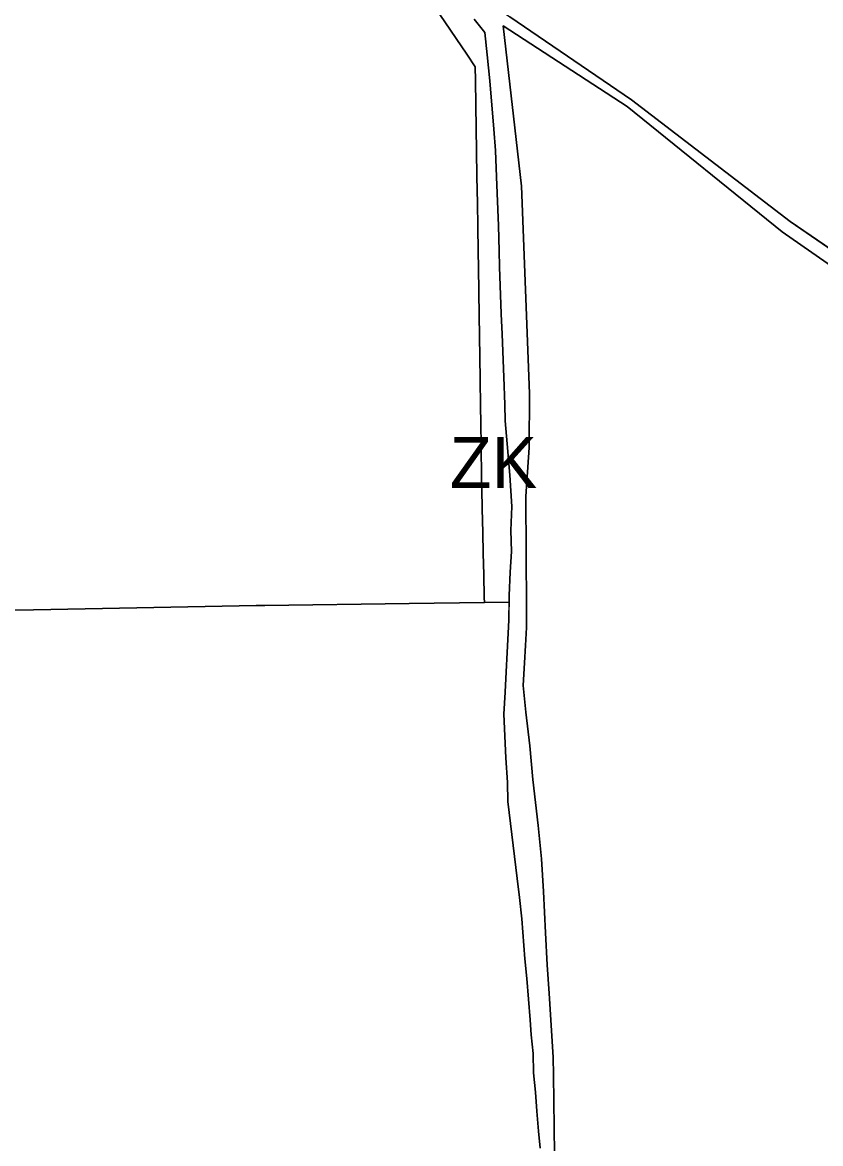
# Model space of a CAD drawing. Extents: x -555509 to -553005, y -1186756 to -1182560.
# Drawn here: x -554047.8 to -553829.3, y -1184851.2 to -1184544.3 of the extents above; entities that cross this region are included whole.
import ezdxf

# ---------------------------------------------------------------- set-up
doc = ezdxf.new("R2010")
doc.units = 0
for name, color, linetype in [('Level 26', 7, 'Continuous'), ('Level 59', 7, 'Continuous'), ('OBRYS_PLOCH', 7, 'Continuous'), ('stav_AP', 7, 'Continuous'), ('stav_AT', 7, 'Continuous'), ('stav_ZK', 7, 'Continuous')]:
    doc.layers.add(name, color=color, linetype=linetype)

msp = doc.modelspace()

# ---------------------------------------------------------------- linework, layer by layer
at = {"layer": 'Level 26'}
for p, q in [((-553881.11, -1184565.44), (-553914.41, -1184542.78)), ((-553911.19, -1184589.14), (-553916.19, -1184545.2)), ((-553916.19, -1184545.2), (-553882.3, -1184567.34)), ((-553837.69, -1184598.76), (-553881.11, -1184565.44)), ((-553882.3, -1184567.34), (-553839.83, -1184601.57)), ((-553918.79, -1184573.46), (-553918.31, -1184579.35)), ((-553918.31, -1184579.35), (-553918.07, -1184586.52)), ((-553908.98, -1184645.9), (-553911.19, -1184589.14)), ((-553803.8, -1184622.03), (-553837.69, -1184598.76)), ((-553839.83, -1184601.57), (-553806.23, -1184625.08)), ((-553917.31, -1184606.77), (-553917.27, -1184611.19)), ((-553917.27, -1184611.19), (-553916.78, -1184624.01)), ((-553916.78, -1184624.01), (-553916.48, -1184629.6)), ((-553909.12, -1184660.61), (-553908.98, -1184645.9)), ((-553910.02, -1184674.09), (-553909.12, -1184660.61)), ((-553914.43, -1184668.19), (-553913.86, -1184676.76)), ((-553909.89, -1184689.55), (-553910.02, -1184674.09)), ((-553913.86, -1184676.76), (-553914.11, -1184683.41)), ((-553909.84, -1184704.54), (-553909.89, -1184689.55)), ((-553914.6, -1184701.16), (-553914.68, -1184707.49)), ((-553909.82, -1184709.89), (-553909.84, -1184704.54)), ((-553910.1, -1184714.83), (-553909.82, -1184709.89)), ((-553910.38, -1184719.64), (-553910.1, -1184714.83)), ((-553910.73, -1184725.83), (-553910.38, -1184719.64)), ((-553909.98, -1184733.08), (-553910.73, -1184725.83)), ((-553908.96, -1184742.29), (-553909.98, -1184733.08)), ((-553908.11, -1184751.52), (-553908.96, -1184742.29)), ((-553906.67, -1184764.14), (-553908.11, -1184751.52)), ((-553905.75, -1184773.22), (-553906.67, -1184764.14)), ((-553905.22, -1184782.2), (-553905.75, -1184773.22)), ((-553904.59, -1184793.52), (-553905.22, -1184782.2)), ((-553904.14, -1184802.28), (-553904.59, -1184793.52)), ((-553903.64, -1184810.15), (-553904.14, -1184802.28)), ((-553902.52, -1184827.53), (-553903.64, -1184810.15)), ((-553902.44, -1184832.5), (-553902.52, -1184827.53)), ((-553902.25, -1184846.67), (-553902.44, -1184832.5)), ((-553902.14, -1184854.22), (-553902.25, -1184846.67))]:
    msp.add_line(p, q, dxfattribs=at)
for points in [[(-553924.15, -1184543.36), (-553921.25, -1184547.01), (-553920.61, -1184553.15), (-553919.86, -1184560.27), (-553918.79, -1184573.46)], [(-553918.07, -1184586.52), (-553917.5, -1184599.96), (-553917.31, -1184606.77)], [(-553916.48, -1184629.6), (-553916.08, -1184641.35), (-553915.74, -1184648.9), (-553915.7, -1184653.31), (-553915.13, -1184659.63), (-553914.43, -1184668.19)], [(-553914.11, -1184683.41), (-553913.94, -1184689.11), (-553914.3, -1184694.82), (-553914.6, -1184701.16)], [(-553914.68, -1184707.49), (-553914.7, -1184707.94), (-553915.09, -1184716.81), (-553915.38, -1184722.04), (-553915.68, -1184727.61), (-553916.05, -1184733.65), (-553915.51, -1184745.58), (-553915.06, -1184752.33), (-553914.93, -1184757.57), (-553912.36, -1184778.63), (-553911.73, -1184783.86), (-553911.1, -1184789.69), (-553910.28, -1184800.63), (-553909.75, -1184806.01), (-553908.82, -1184817.35), (-553908.57, -1184821.45), (-553908.05, -1184826.55), (-553907.89, -1184831.84), (-553907.4, -1184837.11), (-553906.96, -1184842.33), (-553906.53, -1184847.81), (-553906.08, -1184852.45)]]:
    msp.add_lwpolyline(points, dxfattribs=at)
at = {"layer": 'OBRYS_PLOCH'}
for p, q in [((-553881.11, -1184565.44), (-553914.41, -1184542.78)), ((-553911.19, -1184589.14), (-553916.19, -1184545.2)), ((-553916.19, -1184545.2), (-553882.3, -1184567.34)), ((-553882.3, -1184567.34), (-553916.19, -1184545.2)), ((-553916.19, -1184545.2), (-553911.19, -1184589.14)), ((-553837.69, -1184598.76), (-553881.11, -1184565.44)), ((-553882.3, -1184567.34), (-553839.83, -1184601.57)), ((-553839.83, -1184601.57), (-553882.3, -1184567.34)), ((-553918.31, -1184579.35), (-553918.79, -1184573.46)), ((-553918.79, -1184573.46), (-553918.31, -1184579.35)), ((-553918.07, -1184586.52), (-553918.31, -1184579.35)), ((-553918.31, -1184579.35), (-553918.07, -1184586.52)), ((-553908.98, -1184645.9), (-553911.19, -1184589.14)), ((-553911.19, -1184589.14), (-553908.98, -1184645.9)), ((-553803.8, -1184622.03), (-553837.69, -1184598.76)), ((-553839.83, -1184601.57), (-553806.23, -1184625.08)), ((-553806.23, -1184625.08), (-553839.83, -1184601.57)), ((-553917.27, -1184611.19), (-553917.31, -1184606.77)), ((-553917.31, -1184606.77), (-553917.27, -1184611.19)), ((-553916.78, -1184624.01), (-553917.27, -1184611.19)), ((-553917.27, -1184611.19), (-553916.78, -1184624.01)), ((-553916.48, -1184629.6), (-553916.78, -1184624.01)), ((-553916.78, -1184624.01), (-553916.48, -1184629.6)), ((-553909.12, -1184660.61), (-553908.98, -1184645.9)), ((-553908.98, -1184645.9), (-553909.12, -1184660.61)), ((-553910.02, -1184674.09), (-553909.12, -1184660.61)), ((-553909.12, -1184660.61), (-553910.02, -1184674.09)), ((-553913.86, -1184676.76), (-553914.43, -1184668.19)), ((-553914.43, -1184668.19), (-553913.86, -1184676.76)), ((-553909.89, -1184689.55), (-553910.02, -1184674.09)), ((-553910.02, -1184674.09), (-553909.89, -1184689.55)), ((-553914.11, -1184683.41), (-553913.86, -1184676.76)), ((-553913.86, -1184676.76), (-553914.11, -1184683.41)), ((-553909.84, -1184704.54), (-553909.89, -1184689.55)), ((-553909.89, -1184689.55), (-553909.84, -1184704.54)), ((-553921.37, -1184703.05), (-553914.62, -1184702.96)), ((-553914.62, -1184702.96), (-553921.37, -1184703.05)), ((-553914.6, -1184701.16), (-553914.68, -1184707.49)), ((-553914.68, -1184707.49), (-553914.62, -1184702.96)), ((-553914.62, -1184702.96), (-553914.6, -1184701.16)), ((-553909.82, -1184709.89), (-553909.84, -1184704.54)), ((-553909.84, -1184704.54), (-553909.82, -1184709.89)), ((-553910.1, -1184714.83), (-553909.82, -1184709.89)), ((-553909.82, -1184709.89), (-553910.1, -1184714.83)), ((-553910.38, -1184719.64), (-553910.1, -1184714.83)), ((-553910.1, -1184714.83), (-553910.38, -1184719.64)), ((-553910.73, -1184725.83), (-553910.38, -1184719.64)), ((-553910.38, -1184719.64), (-553910.73, -1184725.83)), ((-553909.98, -1184733.08), (-553910.73, -1184725.83)), ((-553910.73, -1184725.83), (-553909.98, -1184733.08)), ((-553908.96, -1184742.29), (-553909.98, -1184733.08)), ((-553909.98, -1184733.08), (-553908.96, -1184742.29)), ((-553908.11, -1184751.52), (-553908.96, -1184742.29)), ((-553908.96, -1184742.29), (-553908.11, -1184751.52)), ((-553906.67, -1184764.14), (-553908.11, -1184751.52)), ((-553908.11, -1184751.52), (-553906.67, -1184764.14)), ((-553905.75, -1184773.22), (-553906.67, -1184764.14)), ((-553906.67, -1184764.14), (-553905.75, -1184773.22)), ((-553905.22, -1184782.2), (-553905.75, -1184773.22)), ((-553905.75, -1184773.22), (-553905.22, -1184782.2)), ((-553904.59, -1184793.52), (-553905.22, -1184782.2)), ((-553905.22, -1184782.2), (-553904.59, -1184793.52)), ((-553904.14, -1184802.28), (-553904.59, -1184793.52)), ((-553904.59, -1184793.52), (-553904.14, -1184802.28)), ((-553903.64, -1184810.15), (-553904.14, -1184802.28)), ((-553904.14, -1184802.28), (-553903.64, -1184810.15)), ((-553902.52, -1184827.53), (-553903.64, -1184810.15)), ((-553903.64, -1184810.15), (-553902.52, -1184827.53)), ((-553902.44, -1184832.5), (-553902.52, -1184827.53)), ((-553902.52, -1184827.53), (-553902.44, -1184832.5)), ((-553902.25, -1184846.67), (-553902.44, -1184832.5)), ((-553902.44, -1184832.5), (-553902.25, -1184846.67)), ((-553902.14, -1184854.22), (-553902.25, -1184846.67)), ((-553902.25, -1184846.67), (-553902.14, -1184854.22))]:
    msp.add_line(p, q, dxfattribs=at)
for points in [[(-553983.73, -1184527.21), (-553983.69, -1184531.19), (-553983.64, -1184535.76), (-553957.28, -1184537.01), (-553933.93, -1184541.57), (-553933.57, -1184542.11), (-553926.18, -1184552.98), (-553923.85, -1184556.42), (-553923.79, -1184560.15), (-553923.59, -1184573.42), (-553923.5, -1184579.36), (-553923.39, -1184586.58), (-553923.28, -1184593.78), (-553923.19, -1184600.13)], [(-553923.19, -1184600.13), (-553923.28, -1184593.78), (-553923.39, -1184586.58), (-553923.5, -1184579.36), (-553923.59, -1184573.42), (-553923.79, -1184560.15), (-553923.85, -1184556.42), (-553926.18, -1184552.98), (-553933.57, -1184542.11), (-553933.93, -1184541.57), (-553957.28, -1184537.01), (-553983.64, -1184535.76), (-553983.69, -1184531.19), (-553983.73, -1184527.21)], [(-553928.84, -1184533.21), (-553926.52, -1184534.32), (-553919.83, -1184538.99), (-553914.41, -1184542.78), (-553881.11, -1184565.44), (-553837.69, -1184598.76), (-553803.8, -1184622.03)], [(-553918.79, -1184573.46), (-553919.86, -1184560.27), (-553920.61, -1184553.15), (-553921.25, -1184547.01), (-553924.15, -1184543.36)], [(-553924.15, -1184543.36), (-553921.25, -1184547.01), (-553920.61, -1184553.15), (-553919.86, -1184560.27), (-553918.79, -1184573.46)], [(-553917.31, -1184606.77), (-553917.5, -1184599.96), (-553918.07, -1184586.52)], [(-553918.07, -1184586.52), (-553917.5, -1184599.96), (-553917.31, -1184606.77)], [(-553923.19, -1184600.13), (-553923.08, -1184606.99), (-553923.02, -1184611.45), (-553922.82, -1184624.47), (-553922.74, -1184630.05), (-553922.56, -1184641.92), (-553922.44, -1184649.42), (-553922.38, -1184653.86), (-553922.28, -1184660.24), (-553922.15, -1184668.86), (-553922.1, -1184672.06), (-553921.97, -1184677.47), (-553921.82, -1184683.92), (-553921.68, -1184689.7), (-553921.55, -1184695.45), (-553921.4, -1184701.7), (-553921.37, -1184703.05)], [(-553921.37, -1184703.05), (-553921.4, -1184701.7), (-553921.55, -1184695.45), (-553921.68, -1184689.7), (-553921.82, -1184683.92), (-553921.97, -1184677.47), (-553922.1, -1184672.06), (-553922.15, -1184668.86), (-553922.28, -1184660.24), (-553922.38, -1184653.86), (-553922.44, -1184649.42), (-553922.56, -1184641.92), (-553922.74, -1184630.05), (-553922.82, -1184624.47), (-553923.02, -1184611.45), (-553923.08, -1184606.99), (-553923.19, -1184600.13)], [(-553914.43, -1184668.19), (-553915.13, -1184659.63), (-553915.7, -1184653.31), (-553915.74, -1184648.9), (-553916.08, -1184641.35), (-553916.48, -1184629.6)], [(-553916.48, -1184629.6), (-553916.08, -1184641.35), (-553915.74, -1184648.9), (-553915.7, -1184653.31), (-553915.13, -1184659.63), (-553914.43, -1184668.19)], [(-553914.6, -1184701.16), (-553914.3, -1184694.82), (-553913.94, -1184689.11), (-553914.11, -1184683.41)], [(-553914.11, -1184683.41), (-553913.94, -1184689.11), (-553914.3, -1184694.82), (-553914.6, -1184701.16)], [(-553921.37, -1184703.05), (-553942, -1184703.34), (-553981.52, -1184703.89), (-553983.81, -1184703.93), (-554016.49, -1184704.55), (-554044.77, -1184705.08), (-554050.76, -1184705.2), (-554089.74, -1184705.97), (-554097.76, -1184706.13), (-554133.71, -1184706.84), (-554215.34, -1184709.13)], [(-554097.76, -1184706.13), (-554089.74, -1184705.97), (-554050.76, -1184705.2), (-554044.77, -1184705.08), (-554016.49, -1184704.55), (-553983.81, -1184703.93), (-553981.52, -1184703.89), (-553942, -1184703.34), (-553921.37, -1184703.05)], [(-553914.68, -1184707.49), (-553914.7, -1184707.94), (-553915.09, -1184716.81), (-553915.38, -1184722.04), (-553915.68, -1184727.61), (-553916.05, -1184733.65), (-553915.51, -1184745.58), (-553915.06, -1184752.33), (-553914.93, -1184757.57), (-553912.36, -1184778.63), (-553911.73, -1184783.86), (-553911.1, -1184789.69), (-553910.28, -1184800.63), (-553909.75, -1184806.01), (-553908.82, -1184817.35), (-553908.57, -1184821.45), (-553908.05, -1184826.55), (-553907.89, -1184831.84), (-553907.4, -1184837.11), (-553906.96, -1184842.33), (-553906.53, -1184847.81), (-553906.08, -1184852.45)], [(-553906.08, -1184852.45), (-553906.53, -1184847.81), (-553906.96, -1184842.33), (-553907.4, -1184837.11), (-553907.89, -1184831.84), (-553908.05, -1184826.55), (-553908.57, -1184821.45), (-553908.82, -1184817.35), (-553909.75, -1184806.01), (-553910.28, -1184800.63), (-553911.1, -1184789.69), (-553911.73, -1184783.86), (-553912.36, -1184778.63), (-553914.93, -1184757.57), (-553915.06, -1184752.33), (-553915.51, -1184745.58), (-553916.05, -1184733.65), (-553915.68, -1184727.61), (-553915.38, -1184722.04), (-553915.09, -1184716.81), (-553914.7, -1184707.94), (-553914.68, -1184707.49)]]:
    msp.add_lwpolyline(points, dxfattribs=at)
at = {"layer": 'stav_AP'}
for p, q in [((-553914.62, -1184702.96), (-553921.37, -1184703.05)), ((-553914.68, -1184707.49), (-553914.62, -1184702.96)), ((-553914.7, -1184707.94), (-553914.68, -1184707.49)), ((-553910.28, -1184800.63), (-553911.1, -1184789.69)), ((-553909.75, -1184806.01), (-553910.28, -1184800.63)), ((-553908.82, -1184817.35), (-553909.75, -1184806.01)), ((-553908.57, -1184821.45), (-553908.82, -1184817.35)), ((-553906.96, -1184842.33), (-553907.4, -1184837.11)), ((-553906.53, -1184847.81), (-553906.96, -1184842.33)), ((-553906.08, -1184852.45), (-553906.53, -1184847.81))]:
    msp.add_line(p, q, dxfattribs=at)
for points in [[(-553981.52, -1184703.89), (-553983.81, -1184703.93), (-554016.49, -1184704.55)], [(-553921.37, -1184703.05), (-553942, -1184703.34), (-553981.52, -1184703.89)], [(-554016.49, -1184704.55), (-554044.77, -1184705.08), (-554050.76, -1184705.2)], [(-553915.38, -1184722.04), (-553915.09, -1184716.81), (-553914.7, -1184707.94)], [(-553916.05, -1184733.65), (-553915.68, -1184727.61), (-553915.38, -1184722.04)], [(-553911.1, -1184789.69), (-553911.73, -1184783.86), (-553912.36, -1184778.63), (-553914.93, -1184757.57), (-553915.06, -1184752.33), (-553915.51, -1184745.58), (-553916.05, -1184733.65)], [(-553907.4, -1184837.11), (-553907.89, -1184831.84), (-553908.05, -1184826.55), (-553908.57, -1184821.45)]]:
    msp.add_lwpolyline(points, dxfattribs=at)
at = {"layer": 'stav_AT'}
for p, q in [((-553882.3, -1184567.34), (-553916.19, -1184545.2)), ((-553916.19, -1184545.2), (-553911.19, -1184589.14)), ((-553839.83, -1184601.57), (-553882.3, -1184567.34)), ((-553911.19, -1184589.14), (-553908.98, -1184645.9)), ((-553806.23, -1184625.08), (-553839.83, -1184601.57)), ((-553908.98, -1184645.9), (-553909.12, -1184660.61)), ((-553909.12, -1184660.61), (-553910.02, -1184674.09)), ((-553910.02, -1184674.09), (-553909.89, -1184689.55)), ((-553909.89, -1184689.55), (-553909.84, -1184704.54)), ((-553909.84, -1184704.54), (-553909.82, -1184709.89)), ((-553909.82, -1184709.89), (-553910.1, -1184714.83)), ((-553910.1, -1184714.83), (-553910.38, -1184719.64)), ((-553910.38, -1184719.64), (-553910.73, -1184725.83)), ((-553910.73, -1184725.83), (-553909.98, -1184733.08)), ((-553909.98, -1184733.08), (-553908.96, -1184742.29)), ((-553908.96, -1184742.29), (-553908.11, -1184751.52)), ((-553908.11, -1184751.52), (-553906.67, -1184764.14)), ((-553906.67, -1184764.14), (-553905.75, -1184773.22)), ((-553905.75, -1184773.22), (-553905.22, -1184782.2)), ((-553905.22, -1184782.2), (-553904.59, -1184793.52)), ((-553904.59, -1184793.52), (-553904.14, -1184802.28)), ((-553904.14, -1184802.28), (-553903.64, -1184810.15)), ((-553903.64, -1184810.15), (-553902.52, -1184827.53)), ((-553902.52, -1184827.53), (-553902.44, -1184832.5)), ((-553902.44, -1184832.5), (-553902.25, -1184846.67)), ((-553902.25, -1184846.67), (-553902.14, -1184854.22))]:
    msp.add_line(p, q, dxfattribs=at)
for points in [[(-553923.19, -1184600.13), (-553923.28, -1184593.78), (-553923.39, -1184586.58), (-553923.5, -1184579.36), (-553923.59, -1184573.42), (-553923.79, -1184560.15), (-553923.85, -1184556.42), (-553926.18, -1184552.98), (-553933.57, -1184542.11), (-553933.93, -1184541.57), (-553957.28, -1184537.01), (-553983.64, -1184535.76), (-553983.69, -1184531.19), (-553983.73, -1184527.21)], [(-553928.84, -1184533.21), (-553926.52, -1184534.32), (-553919.83, -1184538.99), (-553914.41, -1184542.78), (-553881.11, -1184565.44), (-553837.69, -1184598.76), (-553803.8, -1184622.03)], [(-553921.37, -1184703.05), (-553921.4, -1184701.7), (-553921.55, -1184695.45), (-553921.68, -1184689.7), (-553921.82, -1184683.92), (-553921.97, -1184677.47), (-553922.1, -1184672.06), (-553922.15, -1184668.86), (-553922.28, -1184660.24), (-553922.38, -1184653.86), (-553922.44, -1184649.42), (-553922.56, -1184641.92), (-553922.74, -1184630.05), (-553922.82, -1184624.47), (-553923.02, -1184611.45), (-553923.08, -1184606.99), (-553923.19, -1184600.13)], [(-554097.76, -1184706.13), (-554089.74, -1184705.97), (-554050.76, -1184705.2), (-554044.77, -1184705.08), (-554016.49, -1184704.55), (-553983.81, -1184703.93), (-553981.52, -1184703.89), (-553942, -1184703.34), (-553921.37, -1184703.05)]]:
    msp.add_lwpolyline(points, dxfattribs=at)
at = {"layer": 'stav_ZK'}
for p, q in [((-553918.31, -1184579.35), (-553918.79, -1184573.46)), ((-553918.07, -1184586.52), (-553918.31, -1184579.35)), ((-553917.27, -1184611.19), (-553917.31, -1184606.77)), ((-553916.78, -1184624.01), (-553917.27, -1184611.19)), ((-553916.48, -1184629.6), (-553916.78, -1184624.01)), ((-553913.86, -1184676.76), (-553914.43, -1184668.19)), ((-553914.11, -1184683.41), (-553913.86, -1184676.76)), ((-553921.37, -1184703.05), (-553914.62, -1184702.96)), ((-553914.62, -1184702.96), (-553914.6, -1184701.16))]:
    msp.add_line(p, q, dxfattribs=at)
for points in [[(-553983.73, -1184527.21), (-553983.69, -1184531.19), (-553983.64, -1184535.76), (-553957.28, -1184537.01), (-553933.93, -1184541.57), (-553933.57, -1184542.11), (-553926.18, -1184552.98), (-553923.85, -1184556.42), (-553923.79, -1184560.15), (-553923.59, -1184573.42), (-553923.5, -1184579.36), (-553923.39, -1184586.58), (-553923.28, -1184593.78), (-553923.19, -1184600.13)], [(-553918.79, -1184573.46), (-553919.86, -1184560.27), (-553920.61, -1184553.15), (-553921.25, -1184547.01), (-553924.15, -1184543.36)], [(-553917.31, -1184606.77), (-553917.5, -1184599.96), (-553918.07, -1184586.52)], [(-553923.19, -1184600.13), (-553923.08, -1184606.99), (-553923.02, -1184611.45), (-553922.82, -1184624.47), (-553922.74, -1184630.05), (-553922.56, -1184641.92), (-553922.44, -1184649.42), (-553922.38, -1184653.86), (-553922.28, -1184660.24), (-553922.15, -1184668.86), (-553922.1, -1184672.06), (-553921.97, -1184677.47), (-553921.82, -1184683.92), (-553921.68, -1184689.7), (-553921.55, -1184695.45), (-553921.4, -1184701.7), (-553921.37, -1184703.05)], [(-553914.43, -1184668.19), (-553915.13, -1184659.63), (-553915.7, -1184653.31), (-553915.74, -1184648.9), (-553916.08, -1184641.35), (-553916.48, -1184629.6)], [(-553914.6, -1184701.16), (-553914.3, -1184694.82), (-553913.94, -1184689.11), (-553914.11, -1184683.41)]]:
    msp.add_lwpolyline(points, dxfattribs=at)

# ---------------------------------------------------------------- texts
at = {"layer": 'Level 59'}
msp.add_text('ZK', height=14, dxfattribs=at).set_placement((-553930.83, -1184671.74))

doc.saveas('drawing.dxf')
